Omron CX-Programmer project NuevoProyecto (CX-Programmer 9.50)

# PLC NewPLC1: CP1L-E EM

## Program P1b_Apendice (cyclic task 0)
Local symbols
Etapa_0 10.00 BOOL
Etapa_1 10.01 BOOL
Etapa_2 10.02 BOOL
Etapa_3 10.03 BOOL
Etapa_4 10.04 BOOL
F1 0.01 BOOL
F2 0.02 BOOL
Rd 100.00 BOOL
Ri 100.01 BOOL
m 0.00 BOOL

### Section Sección1_Programa_principal
; Programa principal (Etapas 0 ... 4)

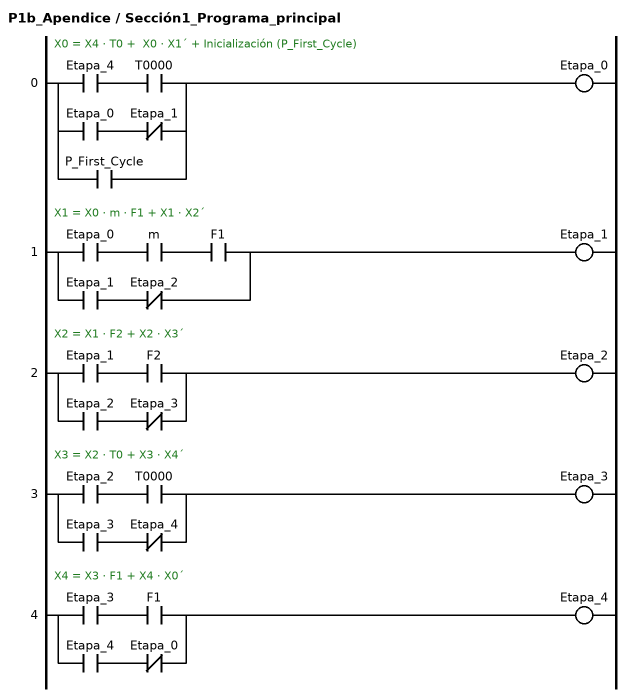
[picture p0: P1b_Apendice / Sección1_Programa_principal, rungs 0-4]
; rung 0: X0 = X4 · T0 +  X0 · X1´ + Inicialización (P_First_Cycle)
LD Etapa_4
AND T0000
LD Etapa_0
ANDNOT Etapa_1
ORLD
OR P_First_Cycle
OUT Etapa_0
; rung 1: X1 = X0 · m · F1 + X1 · X2´
LD Etapa_0
AND m
AND F1
LD Etapa_1
ANDNOT Etapa_2
ORLD
OUT Etapa_1
; rung 2: X2 = X1 · F2 + X2 · X3´
LD Etapa_1
AND F2
LD Etapa_2
ANDNOT Etapa_3
ORLD
OUT Etapa_2
; rung 3: X3 = X2 · T0 + X3 · X4´
LD Etapa_2
AND T0000
LD Etapa_3
ANDNOT Etapa_4
ORLD
OUT Etapa_3
; rung 4: X4 = X3 · F1 + X4 · X0´
LD Etapa_3
AND F1
LD Etapa_4
ANDNOT Etapa_0
ORLD
OUT Etapa_4

### Section Sección2_Temporizador

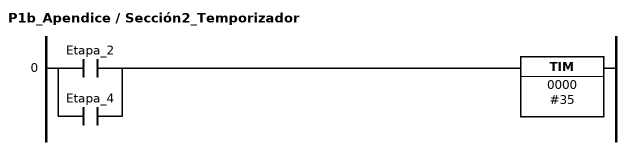
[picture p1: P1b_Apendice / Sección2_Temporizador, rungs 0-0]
; rung 0
LD Etapa_2
OR Etapa_4
TIM 0000 #35

### Section Sección3_Salidas

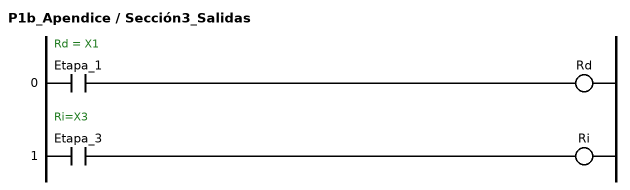
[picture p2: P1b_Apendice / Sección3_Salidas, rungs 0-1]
; rung 0: Rd = X1
LD Etapa_1
OUT Rd
; rung 1: Ri=X3
LD Etapa_3
OUT Ri

### Section Sección4_END
; rung 0: Fin de programa
END(001)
